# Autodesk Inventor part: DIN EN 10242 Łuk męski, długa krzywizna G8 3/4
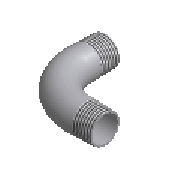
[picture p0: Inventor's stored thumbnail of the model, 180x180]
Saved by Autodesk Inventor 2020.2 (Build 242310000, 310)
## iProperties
Manager: www.cadconsulting.pl
Company: Fabian Stasiak CAD Consulting
Created: 2014-02
Part Number: DIN EN 10242 Łuk męski, długa krzywizna G8 3/4
Material: Żelazo, ciągliwe
Description: Gięcie
Document SubType Name: Modeling
Standard: DIN EN 10242
Designer: F.Stasiak
Standards Organization: DIN
Language: pl-PL
Size Designation: 3/4
Categories: <MemberInstance><Categories><Category DisplayName="Rury cienko- i grubościenne" InternalName="4347fa0f-2144-441d-94cd-e3e15c92b736" Mnemonic="TUBEANDPIPE"><Cate
Density: 7.15 g/cm^3
Appearance: Częściowo polerowana
Catalog Web Link: www.expertbooks.pl
NAME: PIPING: DIN EN 10242 Male Long Sweep Bend G8
DATA: <meta><inlinegroups number="0" deflen="0"></inlinegroups><connections number="2"></connections><angles><a>1.57079632679489</a></angles></meta>
IsCustomPart: 0
Author: F.Stasiak
Subject: Zbiór ćwiczeń. Autodesk Inventor 2020. Kurs Professional
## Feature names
1. Revolution1
2. Revolution2
3. Revolution3
4. Sweep1
## Parameters: MD = 24.117 mm, d26 = 90 deg, d0 = 23.20887 mm, d37 = 90 deg, D = 27.2 mm, B = 14.53 mm, d2 = 0.3124 mm, d3 = 21.795 mm, d4 = 14.53 mm, d5 = 0.3124 mm, d6 = 14.53 mm, d7 = 21.795 mm, d9 = 23.20887 mm, d112 = 0, d114 = 0, DD = 26.441 mm, A = 9.53 mm, d116 = 9.53 mm, d117 = 26.441 mm, d118 = 27.2 mm, d119 = 9.53 mm, d120 = 26.441 mm, d122 = 27.2 mm, d124 = 90 deg, d125 = 0, d126 = 0, Size_Designation = 7.5 mm
